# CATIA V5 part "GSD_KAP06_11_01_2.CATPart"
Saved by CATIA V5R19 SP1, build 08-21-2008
Part number: GSD_BLEND_03
Definition: Beispielmodell für die Funktion Übergang / Blend.
Description: CATIA V5 Flächenmodellierung  Copyright (c) 2009 Maik Hertha IT Consultants
Bounding box of the stored display mesh (mm): x 9.925 to 49.234, y 0 to 39.794, z 0 to 65.132
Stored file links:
  \GSD_BUCH_UEBUNG\GSD_KAP06_11_01_2.CATPart
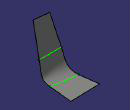
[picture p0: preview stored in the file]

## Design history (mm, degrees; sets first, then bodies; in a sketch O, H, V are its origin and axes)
AxisSystem1 "Absolute Axis System": origin (0, 0, 0), X (1, 0, 0), Y (0, 1, 0), Z (0, 0, 1)
Set1 "Planes.1"
  Plane1: type Equation, A 0, B 1, C 0, Length 0
  Plane2: type Equation, A 0, B 0, C 1, Length 0
  Plane3: type Equation, A 1, B 0, C 0, Length 0
Set2 "Skizzen.1"
  Sketch1 on Plane1, origin (0, 0, 0), H (-1, 0, 0), V (0, 0, 1)
    line L1 (-40.7892, 13.7277) -> (-49.2341, 65.1316)
    line L2 (-49.2341, 65.1316) -> (-29.5293, 63.051)
    line L3 (-29.5293, 63.051) -> (-14.1082, 15.4412)
    line L4 (-14.1082, 15.4412) -> (-40.7892, 13.7277)
  Sketch2 on Plane3, origin (0, 0, 0), H (0, 1, 0), V (0, 0, 1)
    line L1 (16.0881, 21.2572) -> (13.3955, 53.2011)
    line L2 (13.3955, 53.2011) -> (47.42, 60.6669)
    line L3 (47.42, 60.6669) -> (41.3005, 12.9347)
    line L4 (41.3005, 12.9347) -> (16.0881, 21.2572)
  Sketch3 on Plane2, origin (0, 0, 0), H (1, 0, 0), V (0, 1, 0)
    line L1 (12.7396, 17.2746) -> (9.9246, 38.9377)
    line L2 (9.9246, 38.9377) -> (44.561, 39.7944)
    line L3 (44.561, 39.7944) -> (41.746, 12.379)
    line L4 (41.746, 12.379) -> (12.7396, 17.2746)
Set3 "Basisflaechen.1"
  Split1: ToCut Plane1, Cutting Sketch1
  Split2: ToCut Plane3, Cutting Sketch2
  Split3: ToCut Plane2, Cutting Sketch3
Set4 "Blends"
  StIsoparamCurveFeature1 "CATStIsoparamCurveFeatureName": Support Split1, Direction {line type PtDir, Direction (1000, 0, 0), LENGTH 0, LENGTH 10, RefPoint {point type OnSurface, Support Split1, Direction (-0.0529, 0, -0.9986), Length 18.4178}}, Position {point type OnSurface, Support Split1, Direction (-0.0529, 0, -0.9986), Length 18.4178}
  Boundary1: Boundary edge of Split3
  Blend1: StartLimit {blendlimit Support Split1, Curve StIsoparamCurveFeature1, StartLimStartTension 1, StartLimEndTension 1.5}, EndLimit {blendlimit Support Split3, Curve Boundary1}
Body1 (main body)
